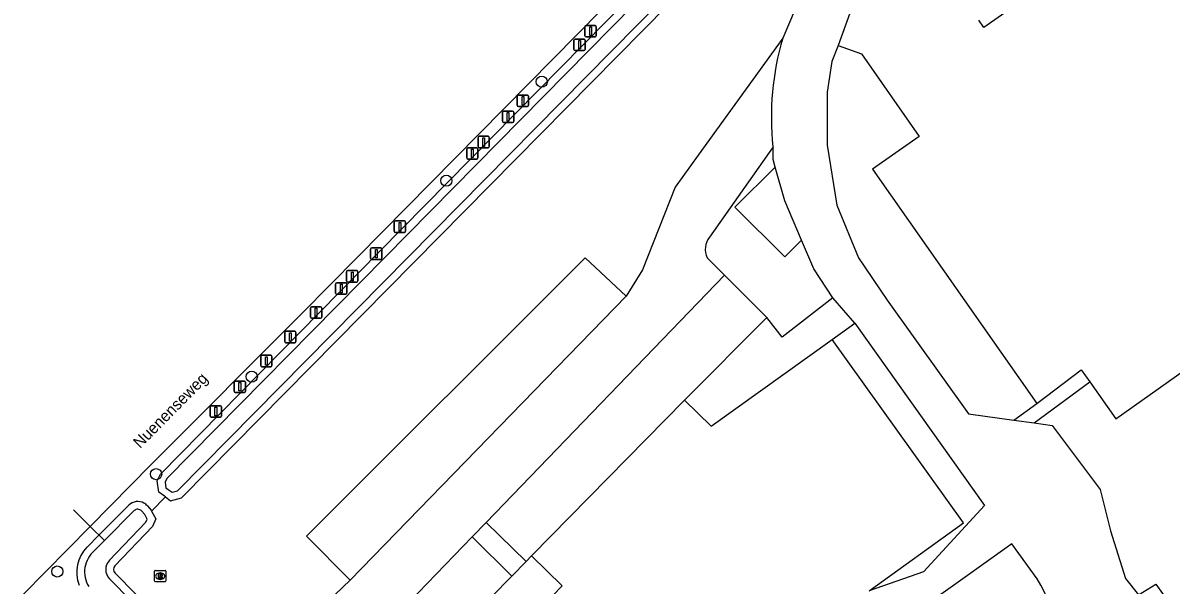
# Model space of a CAD drawing. Extents: x 162791 to 163827, y 385795 to 386523.
# Drawn here: x 162930.7 to 163031.1, y 386221.3 to 386270.5 of the extents above; entities that cross this region are included whole.
import ezdxf

# ---------------------------------------------------------------- set-up
doc = ezdxf.new("R2010")
doc.units = 0
for name, color, linetype in [('IMGEO_Afsluitpaal', 7, 'Continuous'), ('IMGEO_Boom', 7, 'Continuous'), ('IMGEO_Duiker', 7, 'Continuous'), ('IMGEO_Groenvoorziening', 7, 'Continuous'), ('IMGEO_Openbare_ruimte_label', 7, 'Continuous'), ('IMGEO_Pand', 7, 'Continuous'), ('IMGEO_Parkeervlak_halfverhard', 7, 'Continuous'), ('IMGEO_Parkeervlak_open', 7, 'Continuous'), ('IMGEO_Rijbaan_lokaal_open', 7, 'Continuous'), ('IMGEO_Rioolput', 7, 'Continuous'), ('IMGEO_Voetpad_open', 7, 'Continuous'), ('IMGEO_Waterloop', 7, 'Continuous'), ('IMGEO_Woonerf_gesloten', 7, 'Continuous'), ('IMGEO_Woonerf_open', 7, 'Continuous')]:
    doc.layers.add(name, color=color, linetype=linetype)

msp = doc.modelspace()

# ---------------------------------------------------------------- linework, layer by layer
at = {"layer": 'IMGEO_Afsluitpaal'}
for p, q in [((162979.85, 386269.36), (162979.85, 386270.16)), ((162979.85, 386270.16), (162979.85, 386269.36)), ((162979.95, 386270.26), (162980.74, 386270.26)), ((162980.74, 386270.26), (162979.95, 386270.26)), ((162980.84, 386270.16), (162980.84, 386269.36)), ((162980.84, 386269.36), (162980.84, 386270.16)), ((162978.89, 386268.18), (162978.89, 386268.98)), ((162978.89, 386268.98), (162978.89, 386268.18)), ((162978.99, 386269.08), (162979.78, 386269.08)), ((162979.78, 386269.08), (162978.99, 386269.08)), ((162979.88, 386268.98), (162979.88, 386268.18)), ((162979.88, 386268.18), (162979.88, 386268.98)), ((162980.74, 386269.26), (162979.95, 386269.26)), ((162979.95, 386269.26), (162980.74, 386269.26)), ((162979.78, 386268.08), (162978.99, 386268.08)), ((162978.99, 386268.08), (162979.78, 386268.08)), ((162973.92, 386263.28), (162973.92, 386264.08)), ((162973.92, 386264.08), (162973.92, 386263.28)), ((162974.02, 386264.18), (162974.81, 386264.18)), ((162974.81, 386264.18), (162974.02, 386264.18)), ((162974.91, 386264.08), (162974.91, 386263.28)), ((162974.91, 386263.28), (162974.91, 386264.08)), ((162972.63, 386261.88), (162972.63, 386262.68)), ((162972.63, 386262.68), (162972.63, 386261.88)), ((162972.73, 386262.78), (162973.52, 386262.78)), ((162973.52, 386262.78), (162972.73, 386262.78)), ((162973.62, 386262.68), (162973.62, 386261.88)), ((162973.62, 386261.88), (162973.62, 386262.68)), ((162974.81, 386263.18), (162974.02, 386263.18)), ((162974.02, 386263.18), (162974.81, 386263.18)), ((162973.52, 386261.78), (162972.73, 386261.78)), ((162972.73, 386261.78), (162973.52, 386261.78)), ((162970.49, 386259.67), (162970.49, 386260.47)), ((162970.49, 386260.47), (162970.49, 386259.67)), ((162970.59, 386260.57), (162971.38, 386260.57)), ((162971.38, 386260.57), (162970.59, 386260.57)), ((162971.48, 386260.47), (162971.48, 386259.67)), ((162971.48, 386259.67), (162971.48, 386260.47)), ((162969.5, 386258.67), (162969.5, 386259.47)), ((162969.5, 386259.47), (162969.5, 386258.67)), ((162969.6, 386259.57), (162970.38, 386259.57)), ((162970.38, 386259.57), (162969.6, 386259.57)), ((162970.48, 386259.47), (162970.48, 386258.67)), ((162970.48, 386258.67), (162970.48, 386259.47)), ((162971.38, 386259.57), (162970.59, 386259.57)), ((162970.59, 386259.57), (162971.38, 386259.57)), ((162970.38, 386258.57), (162969.6, 386258.57)), ((162969.6, 386258.57), (162970.38, 386258.57)), ((162963.16, 386252.26), (162963.16, 386253.06)), ((162963.16, 386253.06), (162963.16, 386252.26)), ((162963.26, 386253.16), (162964.05, 386253.16)), ((162964.05, 386253.16), (162963.26, 386253.16)), ((162964.15, 386253.06), (162964.15, 386252.26)), ((162964.15, 386252.26), (162964.15, 386253.06)), ((162964.05, 386252.16), (162963.26, 386252.16)), ((162963.26, 386252.16), (162964.05, 386252.16)), ((162961.09, 386249.9), (162961.09, 386250.7)), ((162961.09, 386250.7), (162961.09, 386249.9)), ((162961.19, 386250.8), (162961.98, 386250.8)), ((162961.98, 386250.8), (162961.19, 386250.8)), ((162962.08, 386250.7), (162962.08, 386249.9)), ((162962.08, 386249.9), (162962.08, 386250.7)), ((162961.98, 386249.8), (162961.19, 386249.8)), ((162961.19, 386249.8), (162961.98, 386249.8)), ((162958.99, 386247.91), (162958.99, 386248.71)), ((162958.99, 386248.71), (162958.99, 386247.91)), ((162959.09, 386248.81), (162959.88, 386248.81)), ((162959.88, 386248.81), (162959.09, 386248.81)), ((162959.98, 386248.71), (162959.98, 386247.91)), ((162959.98, 386247.91), (162959.98, 386248.71)), ((162958.03, 386246.84), (162958.03, 386247.64)), ((162958.03, 386247.64), (162958.03, 386246.84)), ((162958.13, 386247.74), (162958.92, 386247.74)), ((162958.92, 386247.74), (162958.13, 386247.74)), ((162959.02, 386247.64), (162959.02, 386246.84)), ((162959.02, 386246.84), (162959.02, 386247.64)), ((162959.88, 386247.81), (162959.09, 386247.81)), ((162959.09, 386247.81), (162959.88, 386247.81)), ((162958.92, 386246.74), (162958.13, 386246.74)), ((162958.13, 386246.74), (162958.92, 386246.74)), ((162955.82, 386244.74), (162955.82, 386245.54)), ((162955.82, 386245.54), (162955.82, 386244.74)), ((162955.92, 386245.64), (162956.71, 386245.64)), ((162956.71, 386245.64), (162955.92, 386245.64)), ((162956.81, 386245.54), (162956.81, 386244.74)), ((162956.81, 386244.74), (162956.81, 386245.54)), ((162956.71, 386244.64), (162955.92, 386244.64)), ((162955.92, 386244.64), (162956.71, 386244.64)), ((162953.57, 386242.6), (162953.57, 386243.4)), ((162953.57, 386243.4), (162953.57, 386242.6)), ((162953.67, 386243.5), (162954.46, 386243.5)), ((162954.46, 386243.5), (162953.67, 386243.5)), ((162954.56, 386243.4), (162954.56, 386242.6)), ((162954.56, 386242.6), (162954.56, 386243.4)), ((162954.46, 386242.5), (162953.67, 386242.5)), ((162953.67, 386242.5), (162954.46, 386242.5)), ((162951.47, 386240.5), (162951.47, 386241.3)), ((162951.47, 386241.3), (162951.47, 386240.5)), ((162951.57, 386241.4), (162952.36, 386241.4)), ((162952.36, 386241.4), (162951.57, 386241.4)), ((162952.46, 386241.3), (162952.46, 386240.5)), ((162952.46, 386240.5), (162952.46, 386241.3)), ((162952.36, 386240.4), (162951.57, 386240.4)), ((162951.57, 386240.4), (162952.36, 386240.4)), ((162949.15, 386238.25), (162949.15, 386239.05)), ((162949.15, 386239.05), (162949.15, 386238.25)), ((162949.25, 386239.15), (162950.04, 386239.15)), ((162950.04, 386239.15), (162949.25, 386239.15)), ((162950.14, 386239.05), (162950.14, 386238.25)), ((162950.14, 386238.25), (162950.14, 386239.05)), ((162950.04, 386238.15), (162949.25, 386238.15)), ((162949.25, 386238.15), (162950.04, 386238.15)), ((162947.05, 386236.08), (162947.05, 386236.88)), ((162947.05, 386236.88), (162947.05, 386236.08)), ((162947.15, 386236.98), (162947.94, 386236.98)), ((162947.94, 386236.98), (162947.15, 386236.98)), ((162948.04, 386236.88), (162948.04, 386236.08)), ((162948.04, 386236.08), (162948.04, 386236.88)), ((162947.94, 386235.98), (162947.15, 386235.98)), ((162947.15, 386235.98), (162947.94, 386235.98))]:
    msp.add_line(p, q, dxfattribs=at)
for points in [[(162980.27, 386270.14), (162980.42, 386270.14), (162980.42, 386269.39), (162980.27, 386269.39), (162980.27, 386270.14)], [(162979.31, 386268.96), (162979.46, 386268.96), (162979.46, 386268.21), (162979.31, 386268.21), (162979.31, 386268.96)], [(162974.34, 386264.05), (162974.49, 386264.05), (162974.49, 386263.3), (162974.34, 386263.3), (162974.34, 386264.05)], [(162973.05, 386262.65), (162973.2, 386262.65), (162973.2, 386261.9), (162973.05, 386261.9), (162973.05, 386262.65)], [(162970.91, 386260.44), (162971.06, 386260.44), (162971.06, 386259.69), (162970.91, 386259.69), (162970.91, 386260.44)], [(162969.91, 386259.45), (162970.07, 386259.45), (162970.07, 386258.7), (162969.91, 386258.7), (162969.91, 386259.45)], [(162963.58, 386253.03), (162963.73, 386253.03), (162963.73, 386252.28), (162963.58, 386252.28), (162963.58, 386253.03)], [(162961.51, 386250.67), (162961.66, 386250.67), (162961.66, 386249.92), (162961.51, 386249.92), (162961.51, 386250.67)], [(162959.41, 386248.68), (162959.56, 386248.68), (162959.56, 386247.93), (162959.41, 386247.93), (162959.41, 386248.68)], [(162958.45, 386247.62), (162958.6, 386247.62), (162958.6, 386246.87), (162958.45, 386246.87), (162958.45, 386247.62)], [(162956.24, 386245.52), (162956.39, 386245.52), (162956.39, 386244.77), (162956.24, 386244.77), (162956.24, 386245.52)], [(162953.99, 386243.38), (162954.14, 386243.38), (162954.14, 386242.63), (162953.99, 386242.63), (162953.99, 386243.38)], [(162951.89, 386241.28), (162952.04, 386241.28), (162952.04, 386240.53), (162951.89, 386240.53), (162951.89, 386241.28)], [(162949.57, 386239.03), (162949.72, 386239.03), (162949.72, 386238.28), (162949.57, 386238.28), (162949.57, 386239.03)], [(162947.47, 386236.85), (162947.62, 386236.85), (162947.62, 386236.1), (162947.47, 386236.1), (162947.47, 386236.85)]]:
    msp.add_lwpolyline(points, dxfattribs=at)
for centre, start, end in [((162979.95, 386270.16), 90, 180), ((162979.95, 386270.16), 90, 180), ((162980.74, 386270.16), 0, 90), ((162980.74, 386270.16), 360, 90), ((162978.99, 386268.98), 90, 180), ((162978.99, 386268.98), 90, 180), ((162979.78, 386268.98), 0, 90), ((162979.78, 386268.98), 360, 90), ((162979.95, 386269.36), 180, 270), ((162979.95, 386269.36), 180, 270), ((162980.74, 386269.36), 270, 0), ((162980.74, 386269.36), 270, 0), ((162978.99, 386268.18), 180, 270), ((162978.99, 386268.18), 180, 270), ((162979.78, 386268.18), 270, 0), ((162979.78, 386268.18), 270, 0), ((162974.02, 386264.08), 90, 180), ((162974.02, 386264.08), 90, 180), ((162974.81, 386264.08), 0, 90), ((162974.81, 386264.08), 360, 90), ((162972.73, 386262.68), 90, 180), ((162972.73, 386262.68), 90, 180), ((162973.52, 386262.68), 0, 90), ((162973.52, 386262.68), 360, 90), ((162974.02, 386263.28), 180, 270), ((162974.02, 386263.28), 180, 270), ((162974.81, 386263.28), 270, 0), ((162974.81, 386263.28), 270, 0), ((162972.73, 386261.88), 180, 270), ((162972.73, 386261.88), 180, 270), ((162973.52, 386261.88), 270, 0), ((162973.52, 386261.88), 270, 0), ((162970.59, 386260.47), 90, 180), ((162970.59, 386260.47), 90, 180), ((162970.59, 386259.67), 180, 270), ((162970.59, 386259.67), 180, 270), ((162971.38, 386260.47), 0, 90), ((162971.38, 386260.47), 360, 90), ((162971.38, 386259.67), 270, 0), ((162971.38, 386259.67), 270, 0), ((162969.6, 386259.47), 90, 180), ((162969.6, 386259.47), 90, 180), ((162969.6, 386258.67), 180, 270), ((162969.6, 386258.67), 180, 270), ((162970.38, 386259.47), 0, 90), ((162970.38, 386259.47), 360, 90), ((162970.38, 386258.67), 270, 0), ((162970.38, 386258.67), 270, 0), ((162963.26, 386253.06), 90, 180), ((162963.26, 386253.06), 90, 180), ((162964.05, 386253.06), 0, 90), ((162964.05, 386253.06), 360, 90), ((162963.26, 386252.26), 180, 270), ((162963.26, 386252.26), 180, 270), ((162964.05, 386252.26), 270, 0), ((162964.05, 386252.26), 270, 0), ((162961.19, 386250.7), 90, 180), ((162961.19, 386250.7), 90, 180), ((162961.98, 386250.7), 0, 90), ((162961.98, 386250.7), 360, 90), ((162961.19, 386249.9), 180, 270), ((162961.19, 386249.9), 180, 270), ((162961.98, 386249.9), 270, 0), ((162961.98, 386249.9), 270, 0), ((162959.09, 386248.71), 90, 180), ((162959.09, 386248.71), 90, 180), ((162959.88, 386248.71), 0, 90), ((162959.88, 386248.71), 360, 90), ((162958.13, 386247.64), 90, 180), ((162958.13, 386247.64), 90, 180), ((162958.92, 386247.64), 0, 90), ((162958.92, 386247.64), 360, 90), ((162959.09, 386247.91), 180, 270), ((162959.09, 386247.91), 180, 270), ((162959.88, 386247.91), 270, 0), ((162959.88, 386247.91), 270, 0), ((162958.13, 386246.84), 180, 270), ((162958.13, 386246.84), 180, 270), ((162958.92, 386246.84), 270, 0), ((162958.92, 386246.84), 270, 0), ((162955.92, 386245.54), 90, 180), ((162955.92, 386245.54), 90, 180), ((162956.71, 386245.54), 0, 90), ((162956.71, 386245.54), 360, 90), ((162955.92, 386244.74), 180, 270), ((162955.92, 386244.74), 180, 270), ((162956.71, 386244.74), 270, 0), ((162956.71, 386244.74), 270, 0), ((162953.67, 386243.4), 90, 180), ((162953.67, 386243.4), 90, 180), ((162953.67, 386242.6), 180, 270), ((162953.67, 386242.6), 180, 270), ((162954.46, 386243.4), 0, 90), ((162954.46, 386243.4), 360, 90), ((162954.46, 386242.6), 270, 0), ((162954.46, 386242.6), 270, 0), ((162951.57, 386241.3), 90, 180), ((162951.57, 386241.3), 90, 180), ((162952.36, 386241.3), 0, 90), ((162952.36, 386241.3), 360, 90), ((162951.57, 386240.5), 180, 270), ((162951.57, 386240.5), 180, 270), ((162952.36, 386240.5), 270, 0), ((162952.36, 386240.5), 270, 0), ((162949.25, 386239.05), 90, 180), ((162949.25, 386239.05), 90, 180), ((162950.04, 386239.05), 0, 90), ((162950.04, 386239.05), 360, 90), ((162949.25, 386238.25), 180, 270), ((162949.25, 386238.25), 180, 270), ((162950.04, 386238.25), 270, 0), ((162950.04, 386238.25), 270, 0), ((162947.15, 386236.88), 90, 180), ((162947.15, 386236.88), 90, 180), ((162947.94, 386236.88), 0, 90), ((162947.94, 386236.88), 360, 90), ((162947.15, 386236.08), 180, 270), ((162947.15, 386236.08), 180, 270), ((162947.94, 386236.08), 270, 0), ((162947.94, 386236.08), 270, 0)]:
    msp.add_arc(centre, 0.1, start, end, dxfattribs=at)
at = {"layer": 'IMGEO_Boom'}
for centre in [(162976.07, 386265.35), (162967.72, 386256.68), (162950.69, 386239.53), (162942.32, 386231), (162933.67, 386222.48)]:
    msp.add_circle(centre, 0.489, dxfattribs=at)
at = {"layer": 'IMGEO_Duiker'}
msp.add_lwpolyline([(162935.09, 386227.87), (162935.09, 386227.87), (162936.54, 386226.43), (162937.79, 386225.18)], dxfattribs=at)
at = {"layer": 'IMGEO_Groenvoorziening'}
for points in [[(162943.13, 386229.01), (162943.05, 386229.06), (162942.55, 386229.42), (162942.4, 386230.42), (162942.71, 386231.01), (162961.88, 386250.48), (162999.51, 386288.69), (163018.62, 386308.08), (163019.08, 386308.03), (163019.64, 386307.88), (163019.98, 386307.71), (163020.27, 386307.42)], [(162943.13, 386229.01), (162943.59, 386228.67), (162944.55, 386228.94), (162964.86, 386249.52), (163000.49, 386285.64), (163020.58, 386306.01), (163020.6, 386306.51), (163020.55, 386306.99), (163020.44, 386307.25), (163020.27, 386307.42)], [(162941.92, 386227.77), (162943.13, 386229.01)], [(162936.27, 386224.62), (162937.31, 386225.67), (162939.92, 386228.29)], [(162941.92, 386227.77), (162942.28, 386227.09), (162942.01, 386226.42), (162938.71, 386222.97)], [(162941.56, 386228.23), (162941.88, 386227.84), (162941.92, 386227.77)], [(162938.72, 386222.33), (162951.21, 386209.65), (162952.36, 386208.48)]]:
    msp.add_lwpolyline(points, dxfattribs=at)
for centre, radius, start, end in [((162940.71, 386227.49), 1.12, 60.8142, 134.5938), ((162940.69, 386227.48), 1.14, 40.7862, 60.1742), ((162938.47, 386222.44), 3.1, 135.4068, 201.7016), ((162939.05, 386222.65), 0.46, 136.3947, 224.5005)]:
    msp.add_arc(centre, radius, start, end, dxfattribs=at)
at = {"layer": 'IMGEO_Pand'}
for points in [[(162988.57, 386237.48), (162990.89, 386235.2), (163001.49, 386242.78)], [(163004.71, 386220.78), (163012.99, 386226.74), (163001.49, 386242.78)], [(162988.57, 386237.48), (162975.18, 386223.84)], [(163004.81, 386216.06), (162998.84, 386211.87), (163000, 386210.45), (163000.14, 386210.28), (162990.68, 386200.74), (162991.91, 386199.49), (162983.1, 386190.62), (162967.86, 386205.52), (162976.44, 386214.19), (162973.67, 386216.9), (162977.86, 386221.23), (162975.18, 386223.84)]]:
    msp.add_lwpolyline(points, dxfattribs=at)
at = {"layer": 'IMGEO_Parkeervlak_halfverhard'}
for points in [[(162983.46, 386246.58), (162979.88, 386249.93), (162955.49, 386225.56), (162959.31, 386221.73)], [(162971.2, 386226.78), (162992.07, 386248.41)], [(162992.07, 386248.41), (162995.78, 386244.7)], [(162959.31, 386221.73), (162983.46, 386246.58)], [(162962.88, 386218.16), (162969.97, 386225.5)], [(162975.18, 386223.84), (162974.7, 386223.35)], [(162973.45, 386222.08), (162966.27, 386214.77), (162962.88, 386218.16)]]:
    msp.add_lwpolyline(points, dxfattribs=at)
at = {"layer": 'IMGEO_Parkeervlak_open'}
for points in [[(163024.02, 386239.07), (163026.32, 386235.84), (163042.93, 386247.64), (163036.63, 386256.53), (163040.67, 386259.38), (163029.85, 386274.85), (163025.84, 386272.02), (163023.06, 386275.94), (163014.76, 386270.1), (163014.32, 386270.72)], [(163004.96, 386275.17), (163004.64, 386274.75), (163003.04, 386271.35), (163002, 386268.51)], [(163002, 386268.51), (163004.04, 386267.79), (163009.1, 386260.55), (163005.02, 386257.68), (163019.4, 386237.18)]]:
    msp.add_lwpolyline(points, dxfattribs=at)
at = {"layer": 'IMGEO_Rijbaan_lokaal_open'}
msp.add_lwpolyline([(162930.67, 386220.48), (162936.54, 386226.43), (162941.85, 386231.81), (162955.09, 386245.08), (162959.94, 386250), (162987.7, 386278.13), (163000, 386290.61), (163018.25, 386309.14)], dxfattribs=at)
at = {"layer": 'IMGEO_Rioolput'}
for p, q in [((162942.18, 386221.65), (162942.18, 386222.5)), ((162942.25, 386222.58), (162943.1, 386222.58)), ((162943.18, 386222.5), (162943.18, 386221.65)), ((162943.1, 386221.57), (162942.25, 386221.57)), ((162942.69, 386221.8), (162942.66, 386221.8)), ((162942.67, 386222.35), (162942.69, 386222.35))]:
    msp.add_line(p, q, dxfattribs=at)
for points in [[(162942.18, 386221.65), (162942.18, 386222.5)], [(162942.25, 386222.58), (162943.1, 386222.58)], [(162943.18, 386222.5), (162943.18, 386221.65)], [(162943.1, 386221.57), (162942.25, 386221.57)], [(162942.77, 386222.27), (162942.51, 386222.27), (162942.51, 386221.87)], [(162942.51, 386221.87), (162942.64, 386221.87), (162942.64, 386222.04), (162942.65, 386222.04)], [(162942.69, 386222.19), (162942.64, 386222.19), (162942.64, 386222.11)], [(162942.64, 386222.11), (162942.69, 386222.11)], [(162942.7, 386222.01), (162942.77, 386221.87), (162942.91, 386221.87), (162942.84, 386222)]]:
    msp.add_lwpolyline(points, dxfattribs=at)
for centre, radius, start, end in [((162942.25, 386222.5), 0.0765, 91.552, 178.448), ((162942.25, 386222.5), 0.0765, 91.552, 178.448), ((162943.1, 386222.5), 0.0765, 1.552, 88.448), ((162943.1, 386222.5), 0.0765, 1.552, 88.448), ((162942.25, 386221.65), 0.0765, 181.552, 268.448), ((162942.25, 386221.65), 0.0765, 181.552, 268.448), ((162942.65, 386221.98), 0.0533, 26.0293, 88.6989), ((162942.7, 386222.1), 0.0964, 77.0061, 93.1865), ((162942.67, 386222.3), 0.19, 274.7715, 282.9687), ((162942.71, 386222.15), 0.0378, 276.6634, 79.6772), ((162942.77, 386222.16), 0.109, 350.3612, 89.416), ((162942.76, 386222.16), 0.112, 277.5842, 350.9817), ((162942.75, 386221.95), 0.108, 29.5134, 73.7905), ((162943.1, 386221.65), 0.0765, 271.552, 358.448), ((162943.1, 386221.65), 0.0765, 271.552, 358.448)]:
    msp.add_arc(centre, radius, start, end, dxfattribs=at)
for centre, major_axis, ratio, start_param, end_param in [((162942.66, 386222.07), (-0.387, 0.002), 0.722429, 4.712389, 7.853982), ((162942.69, 386222.07), (-0.39, 0.002), 0.717154, 1.570796, 4.712389)]:
    msp.add_ellipse(centre, major_axis=major_axis, ratio=ratio, start_param=start_param, end_param=end_param, dxfattribs=at)
at = {"layer": 'IMGEO_Voetpad_open'}
for points in [[(162998.8, 386251.47), (162997.34, 386250.01), (162992.98, 386254.38), (162996.5, 386257.88)], [(162998.8, 386251.47), (162997.33, 386254.91), (162996.5, 386257.88)], [(163001.54, 386246.44), (162997.11, 386243), (162995.78, 386244.7)], [(163003.46, 386244.2), (163001.54, 386246.44)], [(162995.78, 386244.7), (162988.57, 386237.48)], [(163001.49, 386242.78), (163003.46, 386244.2)], [(163019.4, 386237.18), (163023.28, 386240.13), (163024.02, 386239.07)], [(163019.15, 386235.48), (163024.02, 386239.07)], [(163017.39, 386235.73), (163019.4, 386237.18)], [(163017.39, 386235.73), (163019.15, 386235.48)], [(162969.97, 386225.5), (162971.2, 386226.78)], [(162974.7, 386223.35), (162971.2, 386226.78)], [(162969.97, 386225.5), (162973.45, 386222.08)], [(162974.7, 386223.35), (162973.45, 386222.08)]]:
    msp.add_lwpolyline(points, dxfattribs=at)
at = {"layer": 'IMGEO_Waterloop'}
for points in [[(162943.45, 386229.61), (162943.73, 386229.41), (162944.2, 386229.55), (162964.37, 386250), (163000, 386286.12), (163019.63, 386306.02), (163019.18, 386306.49), (163018.61, 386307.1), (163000, 386288.21), (162962.36, 386250), (162943.26, 386230.61), (162943.11, 386230.31), (162943.18, 386229.81), (162943.45, 386229.61)], [(162940.4, 386227.81), (162937.79, 386225.18), (162936.76, 386224.15), (162936.61, 386223.99), (162936.48, 386223.82), (162936.37, 386223.63), (162936.27, 386223.44), (162936.19, 386223.24), (162936.13, 386223.03), (162936.09, 386222.82), (162936.06, 386222.6), (162936.06, 386222.39), (162936.07, 386222.17), (162936.11, 386221.96), (162936.16, 386221.75), (162936.23, 386221.54), (162936.32, 386221.35), (162936.43, 386221.16)], [(162938.22, 386223.44), (162941.42, 386226.79), (162941.53, 386227.05), (162941.32, 386227.46), (162941.04, 386227.78)], [(162969.49, 386190.12), (162938.23, 386221.85)]]:
    msp.add_lwpolyline(points, dxfattribs=at)
for centre, radius, start, end in [((162940.71, 386227.5), 0.431, 40.4697, 135.0069), ((162939.05, 386222.65), 1.14, 136.3343, 224.459)]:
    msp.add_arc(centre, radius, start, end, dxfattribs=at)
at = {"layer": 'IMGEO_Woonerf_gesloten'}
for points in [[(163028.09, 386299.44), (163027.35, 386299.42), (163023.43, 386298.41), (163018.5, 386296.45), (163015.17, 386293.58), (163006.68, 386285), (163002.81, 386279.81), (162999.23, 386274.07), (162997.17, 386269.16)], [(163002, 386268.51), (163001.46, 386267.12), (163001.04, 386264.44), (163001.04, 386259.78), (163001.9, 386254.55), (163003.8, 386249.94), (163006.3, 386246.24), (163013.42, 386236.29), (163017.39, 386235.73)], [(162996.5, 386257.88), (162996.31, 386258.55), (162996.31, 386259.65)], [(163001.54, 386246.44), (162999.87, 386248.96), (162998.8, 386251.47)], [(163003.46, 386244.2), (163014.83, 386228.27), (163009.48, 386222.44), (163004.71, 386220.78)], [(163019.15, 386235.48), (163020.73, 386235.26), (163024.94, 386229.66), (163025.83, 386226.03), (163027.16, 386221.87), (163028.3, 386220.43), (163029.8, 386221.38), (163032.5, 386217.6), (163027.08, 386213.7)], [(163019.42, 386221.83), (163017.21, 386224.9), (163006.51, 386217.25), (163004.81, 386216.06)]]:
    msp.add_lwpolyline(points, dxfattribs=at)
for centre, radius, start, end in [((163020.46, 386262.26), 24.3, 163.4894, 186.1706), ((163012.77, 386217.32), 8.03, 323.683, 34.1771)]:
    msp.add_arc(centre, radius, start, end, dxfattribs=at)
at = {"layer": 'IMGEO_Woonerf_open'}
for points in [[(162997.17, 386269.16), (162989.77, 386258.92), (162987.74, 386256.11), (162984.89, 386248.89), (162983.46, 386246.58)], [(162996.31, 386259.65), (162990.74, 386251.75)], [(162990.55, 386249.93), (162992.07, 386248.41)], [(162959.31, 386221.73), (162957.98, 386220.46), (162960, 386218.54)]]:
    msp.add_lwpolyline(points, dxfattribs=at)
msp.add_arc((162992.14, 386250.68), 1.76, 142.4566, 205.2081, dxfattribs=at)

# ---------------------------------------------------------------- texts
at = {"layer": 'IMGEO_Openbare_ruimte_label'}
msp.add_text('Nuenenseweg', height=1, rotation=45.3242, dxfattribs=at).set_placement((162940.91, 386233.2))

doc.saveas('drawing.dxf')
